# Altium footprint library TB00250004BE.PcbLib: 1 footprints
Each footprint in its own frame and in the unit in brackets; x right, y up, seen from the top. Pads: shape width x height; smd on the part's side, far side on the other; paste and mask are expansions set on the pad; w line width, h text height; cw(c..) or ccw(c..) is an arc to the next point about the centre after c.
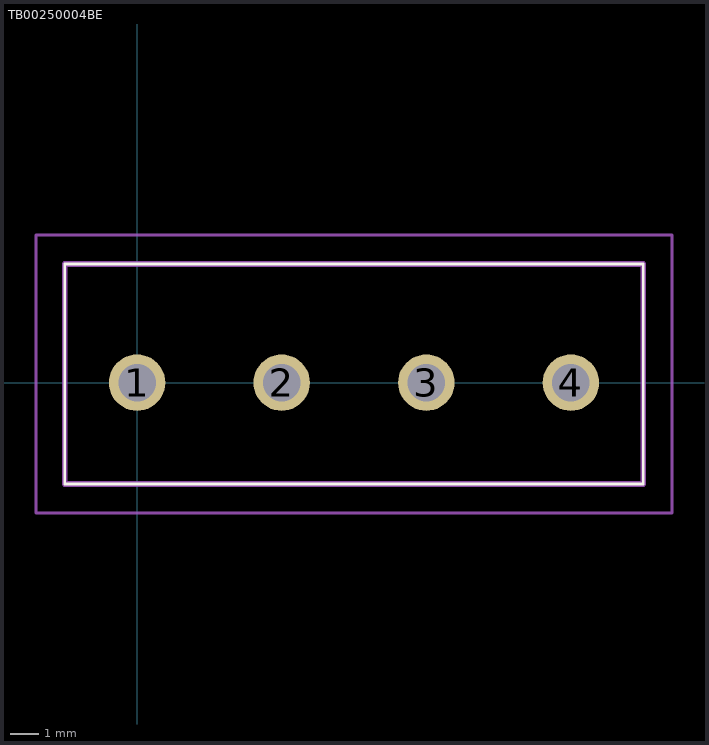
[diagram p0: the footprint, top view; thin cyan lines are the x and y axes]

## TB00250004BE [mm]
pads (4):
  round 1.95 hole 1.3: 1(0,0) 2(5,0) 3(10,0) 4(15,0)
Top Overlay:
  lines w0.1: -2.5,-3.5 17.5,-3.5 17.5,4.1 -2.5,4.1 -2.5,-3.5
Mechanical 15:
  lines w0.2: -2.5,-3.5 17.5,-3.5 17.5,4.1 -2.5,4.1 -2.5,-3.5
Mechanical 20:
  lines w0.1: -3.5,-4.5 18.5,-4.5 18.5,5.1 -3.5,5.1 -3.5,-4.5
